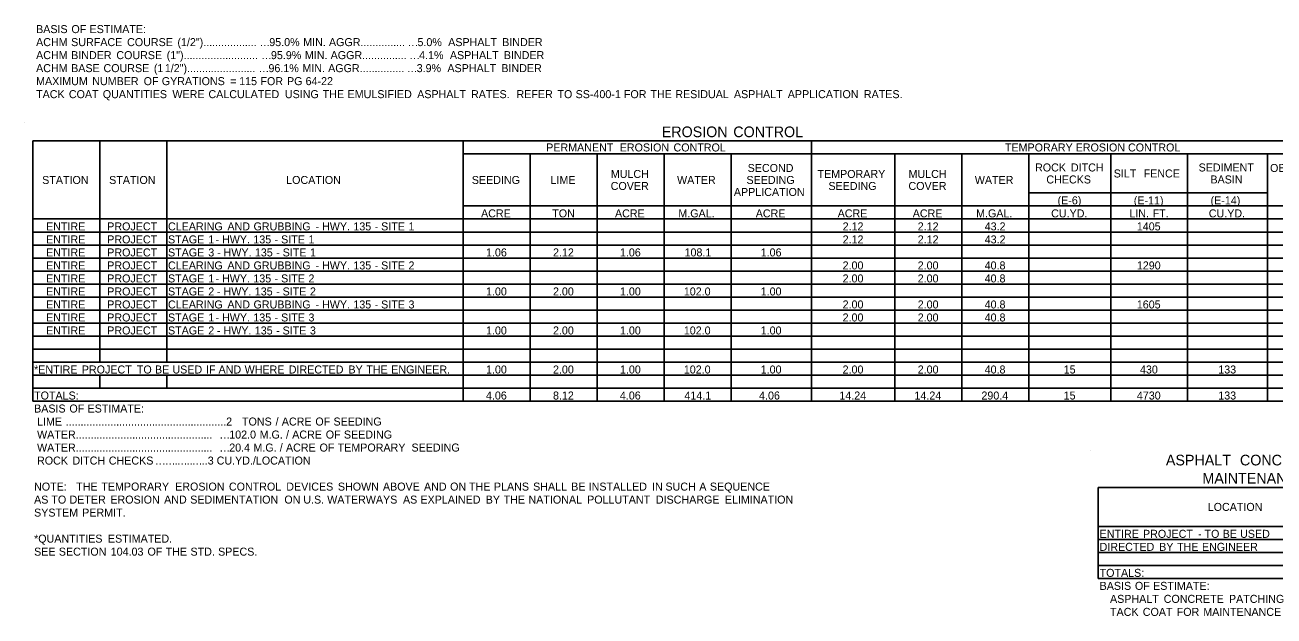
# Model space of a CAD drawing. Extents: x 1955554 to 1962042, y 565952 to 568347.
# Drawn here: x 1958686 to 1959623, y 566010 to 566453 of the extents above; entities that cross this region are included whole.
import ezdxf

# ---------------------------------------------------------------- set-up
doc = ezdxf.new("R2010")
doc.units = 0
doc.layers.add('Default', color=7, linetype='Continuous')
doc.layers.add('R_Border', color=7, linetype='Continuous')

msp = doc.modelspace()

# ---------------------------------------------------------------- linework, layer by layer
at = {"layer": 'Default'}
for p, q in [((1958692.33, 566365.86), (1959744.36, 566365.86)), ((1958692.33, 566170.86), (1958692.33, 566365.86)), ((1958692.33, 566170.86), (1958692.33, 566365.86)), ((1958742.54, 566200.11), (1958742.54, 566365.86)), ((1958792.76, 566200.11), (1958792.76, 566365.86)), ((1959015.06, 566170.86), (1959015.06, 566365.86)), ((1959276.36, 566356.11), (1959276.36, 566365.86)), ((1959276.36, 566170.86), (1959276.36, 566365.86)), ((1959015.06, 566356.11), (1959744.36, 566356.11)), ((1959065.27, 566170.86), (1959065.27, 566356.11)), ((1959115.48, 566170.86), (1959115.48, 566356.11)), ((1959165.69, 566170.86), (1959165.69, 566356.11)), ((1959215.91, 566170.86), (1959215.91, 566356.11)), ((1959338.76, 566170.86), (1959338.76, 566356.11)), ((1959388.97, 566170.86), (1959388.97, 566356.11)), ((1959439.18, 566170.86), (1959439.18, 566356.11)), ((1959500.61, 566170.86), (1959500.61, 566356.11)), ((1959558.13, 566170.86), (1959558.13, 566356.11)), ((1959618.09, 566170.86), (1959618.09, 566356.11)), ((1959439.18, 566326.86), (1959618.09, 566326.86)), ((1959558.13, 566326.86), (1959618.09, 566326.86)), ((1959015.06, 566317.11), (1959744.36, 566317.11)), ((1959065.27, 566170.86), (1959065.27, 566317.11)), ((1959115.48, 566180.61), (1959115.48, 566317.11)), ((1959165.69, 566180.61), (1959165.69, 566317.11)), ((1959215.91, 566180.61), (1959215.91, 566317.11)), ((1959276.36, 566180.61), (1959276.36, 566317.11)), ((1959338.76, 566170.86), (1959338.76, 566317.11)), ((1959388.97, 566170.86), (1959388.97, 566317.11)), ((1959439.18, 566180.61), (1959439.18, 566317.11)), ((1959500.61, 566180.61), (1959500.61, 566317.11)), ((1959558.13, 566170.86), (1959558.13, 566317.11)), ((1959618.09, 566317.11), (1959744.36, 566317.11)), ((1959618.09, 566170.86), (1959618.09, 566317.11)), ((1958692.33, 566307.36), (1959744.36, 566307.36)), ((1958742.54, 566200.11), (1958742.54, 566307.36)), ((1958792.76, 566200.11), (1958792.76, 566307.36)), ((1959015.06, 566200.11), (1959015.06, 566307.36)), ((1958692.33, 566297.61), (1959744.36, 566297.61)), ((1958692.33, 566287.86), (1959744.36, 566287.86)), ((1958692.33, 566278.11), (1959744.36, 566278.11)), ((1958692.33, 566268.36), (1959744.36, 566268.36)), ((1958692.33, 566258.61), (1959744.36, 566258.61)), ((1958692.33, 566248.86), (1959744.36, 566248.86)), ((1958692.33, 566239.11), (1959744.36, 566239.11)), ((1958692.33, 566229.36), (1959744.36, 566229.36)), ((1958692.33, 566219.61), (1959744.36, 566219.61)), ((1958692.33, 566209.86), (1959744.36, 566209.86)), ((1958692.33, 566200.11), (1959744.36, 566200.11)), ((1958692.33, 566190.36), (1959744.36, 566190.36)), ((1958742.54, 566180.61), (1958742.54, 566190.36)), ((1958742.54, 566180.61), (1958742.54, 566190.36)), ((1958792.76, 566180.61), (1958792.76, 566190.36)), ((1958792.76, 566180.61), (1958792.76, 566190.36)), ((1959015.06, 566170.86), (1959015.06, 566190.36)), ((1958692.33, 566180.61), (1959744.36, 566180.61)), ((1959065.27, 566180.61), (1959276.36, 566180.61)), ((1959276.36, 566180.61), (1959338.76, 566180.61)), ((1959338.76, 566180.61), (1959500.61, 566180.61)), ((1959500.61, 566180.61), (1959684.39, 566180.61)), ((1958692.33, 566170.86), (1959744.36, 566170.86)), ((1959491.34, 566106.2), (1959797.98, 566106.2)), ((1959491.34, 566037.95), (1959491.34, 566106.2)), ((1959491.34, 566037.95), (1959491.34, 566106.2)), ((1959491.34, 566076.95), (1959797.98, 566076.95)), ((1959491.34, 566067.2), (1959797.98, 566067.2)), ((1959491.34, 566057.45), (1959797.98, 566057.45)), ((1959491.34, 566047.7), (1959797.98, 566047.7)), ((1959491.34, 566037.95), (1959797.98, 566037.95))]:
    msp.add_line(p, q, dxfattribs=at)
at = {"layer": 'R_Border'}
for p, q in [((1958686.48, 566379.51), (1958686.48, 566379.51)), ((1959485.49, 566133.5), (1959485.49, 566133.5))]:
    msp.add_line(p, q, dxfattribs=at)

# ---------------------------------------------------------------- texts
at = {"layer": 'Default'}
for s, height, p in [('BASIS', 6, (1958694.82, 566446.67)), (' OF', 6, (1958719.08, 566446.67)), (' ESTIMATE:', 6, (1958732.67, 566446.67)), ('ACHM', 6, (1958694.82, 566436.92)), (' SURFACE', 6, (1958718.88, 566436.92)), (' COURSE', 6, (1958760.82, 566436.92)), (' (1/2")..................', 6, (1958798.57, 566436.92)), ('…', 6, (1958862.27, 566436.92)), ('95.0%', 6, (1958869.67, 566436.92)), (' MIN.', 6, (1958892.91, 566436.92)), (' AGGR...............', 6, (1958912.2, 566436.92)), ('…', 6, (1958973.4, 566436.92)), ('5.0%', 6, (1958980.8, 566436.92)), ('  ASPHALT', 6, (1958999.38, 566436.92)), (' BINDER', 6, (1959042.08, 566436.92)), ('ACHM', 6, (1958694.82, 566427.17)), (' BINDER', 6, (1958718.88, 566427.17)), (' COURSE', 6, (1958752.77, 566427.17)), (' (1").........................', 6, (1958790.52, 566427.17)), ('…', 6, (1958863.52, 566427.17)), ('95.9%', 6, (1958870.92, 566427.17)), (' MIN.', 6, (1958894.16, 566427.17)), (' AGGR...............', 6, (1958913.45, 566427.17)), ('…', 6, (1958974.66, 566427.17)), ('4.1%', 6, (1958982.06, 566427.17)), ('  ASPHALT', 6, (1959000.64, 566427.17)), (' BINDER', 6, (1959043.33, 566427.17)), ('ACHM', 6, (1958694.82, 566417.42)), (' BASE', 6, (1958718.88, 566417.42)), (' COURSE', 6, (1958743.13, 566417.42)), (' (1', 6, (1958780.88, 566417.42)), (' 1/2").......................', 6, (1958789.11, 566417.42)), ('…', 6, (1958861.66, 566417.42)), ('96.1%', 6, (1958869.06, 566417.42)), (' MIN.', 6, (1958892.3, 566417.42)), (' AGGR...............', 6, (1958911.59, 566417.42)), ('…', 6, (1958972.8, 566417.42)), ('3.9%', 6, (1958980.2, 566417.42)), ('  ASPHALT', 6, (1958998.78, 566417.42)), (' BINDER', 6, (1959041.47, 566417.42)), ('MAXIMUM', 6, (1958694.82, 566407.67)), (' NUMBER', 6, (1958734.71, 566407.67)), (' OF', 6, (1958773.25, 566407.67)), (' GYRATIONS', 6, (1958786.84, 566407.67)), (' =', 6, (1958838.11, 566407.67)), (' 115', 6, (1958844.87, 566407.67)), (' FOR', 6, (1958860.84, 566407.67)), (' PG', 6, (1958880.75, 566407.67)), (' 64-22', 6, (1958894.67, 566407.67)), ('TACK', 6, (1958694.82, 566397.92)), (' COAT', 6, (1958717.16, 566397.92)), (' QUANTITIES', 6, (1958742.61, 566397.92)), (' WERE', 6, (1958794.81, 566397.92)), (' CALCULATED', 6, (1958821.84, 566397.92)), (' USING', 6, (1958879.16, 566397.92)), (' THE', 6, (1958907.52, 566397.92)), (' EMULSIFIED', 6, (1958926.17, 566397.92)), (' ASPHALT', 6, (1958978.36, 566397.92)), (' RATES.', 6, (1959018.72, 566397.92)), ('  REFER', 6, (1959050.6, 566397.92)), (' TO', 6, (1959083.56, 566397.92)), (' SS-400-1', 6, (1959097.16, 566397.92)), (' FOR', 6, (1959133.35, 566397.92)), (' THE', 6, (1959153.26, 566397.92)), (' RESIDUAL', 6, (1959171.91, 566397.92)), (' ASPHALT', 6, (1959215.87, 566397.92)), (' APPLICATION', 6, (1959256.24, 566397.92)), (' RATES.', 6, (1959313.32, 566397.92)), ('EROSION', 8, (1959164, 566368.68)), (' CONTROL', 8, (1959214.66, 566368.68)), ('PERMANENT', 6, (1959077.32, 566357.98)), (' EROSION', 6, (1959130.25, 566357.98)), (' CONTROL', 6, (1959170.57, 566357.98)), ('TEMPORARY EROSION CONTROL', 6, (1959421.33, 566357.98)), ('MULCH', 6, (1959125.78, 566338.11)), ('SECOND', 6, (1959228.4, 566342.61)), ('TEMPORARY', 6, (1959280.77, 566338.11)), ('MULCH', 6, (1959349.05, 566338.11)), ('ROCK', 6, (1959443.91, 566342.98)), (' DITCH', 6, (1959468.58, 566342.98)), ('SILT', 6, (1959502.88, 566338.48)), ('  FENCE', 6, (1959520.87, 566338.48)), ('SEDIMENT', 6, (1959566.54, 566342.98)), ('OBLITERATION', 6, (1959620.14, 566342.61)), ('STATION', 6, (1958699.38, 566333.61)), ('STATION', 6, (1958749.59, 566333.61)), ('LOCATION', 6, (1958882.35, 566333.61)), ('SEEDING', 6, (1959021.55, 566333.61)), ('LIME', 6, (1959080.57, 566333.61)), ('COVER', 6, (1959125.7, 566329.11)), ('WATER', 6, (1959175.45, 566333.61)), ('SEEDING', 6, (1959227.52, 566333.61)), ('SEEDING', 6, (1959288.94, 566329.11)), ('COVER', 6, (1959348.98, 566329.11)), ('WATER', 6, (1959398.73, 566333.61)), ('CHECKS', 6, (1959452.4, 566333.98)), ('BASIN', 6, (1959575.41, 566333.98)), ('APPLICATION', 6, (1959218.06, 566324.61)), ('(E-6)', 6, (1959460.8, 566318.31)), ('(E-11)', 6, (1959517.95, 566318.31)), ('(E-14)', 6, (1959575.53, 566318.31)), ('ACRE', 6, (1959028.49, 566308.56)), ('TON', 6, (1959081.86, 566308.56)), ('ACRE', 6, (1959128.92, 566308.56)), ('M.GAL.', 6, (1959176.42, 566308.56)), ('ACRE', 6, (1959234.46, 566308.56)), ('ACRE', 6, (1959295.89, 566308.56)), ('ACRE', 6, (1959352.19, 566308.56)), ('M.GAL.', 6, (1959399.7, 566308.56)), ('CU.YD.', 6, (1959455.98, 566308.56)), ('LIN.', 6, (1959514.58, 566308.56)), (' FT.', 6, (1959529.84, 566308.56)), ('CU.YD.', 6, (1959574.19, 566308.56)), ('ENTIRE', 6, (1958702.29, 566298.81)), ('PROJECT', 6, (1958748.17, 566298.81)), ('CLEARING', 6, (1958793.73, 566298.81)), (' AND', 6, (1958836.07, 566298.81)), (' GRUBBING', 6, (1958855.65, 566298.81)), (' -', 6, (1958902.17, 566298.81)), (' HWY.', 6, (1958907.03, 566298.81)), (' 135', 6, (1958930.51, 566298.81)), (' -', 6, (1958946.49, 566298.81)), (' SITE', 6, (1958951.34, 566298.81)), (' 1', 6, (1958971.86, 566298.81)), ('2.12', 6, (1959299.62, 566298.81)), ('2.12', 6, (1959355.93, 566298.81)), ('43.2', 6, (1959406.14, 566298.81)), ('1405', 6, (1959520.22, 566298.81)), ('ENTIRE', 6, (1958702.29, 566289.06)), ('PROJECT', 6, (1958748.17, 566289.06)), ('STAGE', 6, (1958793.73, 566289.06)), (' 1', 6, (1958821.71, 566289.06)), (' -', 6, (1958827.15, 566289.06)), (' HWY.', 6, (1958832.01, 566289.06)), (' 135', 6, (1958855.49, 566289.06)), (' -', 6, (1958871.47, 566289.06)), (' SITE', 6, (1958876.32, 566289.06)), (' 1', 6, (1958896.84, 566289.06)), ('2.12', 6, (1959299.62, 566289.06)), ('2.12', 6, (1959355.93, 566289.06)), ('43.2', 6, (1959406.14, 566289.06)), ('ENTIRE', 6, (1958702.29, 566279.31)), ('PROJECT', 6, (1958748.17, 566279.31)), ('STAGE', 6, (1958793.73, 566279.31)), (' 3', 6, (1958821.71, 566279.31)), (' -', 6, (1958828.31, 566279.31)), (' HWY.', 6, (1958833.17, 566279.31)), (' 135', 6, (1958856.65, 566279.31)), (' -', 6, (1958872.63, 566279.31)), (' SITE', 6, (1958877.49, 566279.31)), (' 1', 6, (1958898, 566279.31)), ('1.06', 6, (1959032.2, 566279.31)), ('2.12', 6, (1959082.44, 566279.31)), ('1.06', 6, (1959132.62, 566279.31)), ('108.1', 6, (1959181.09, 566279.31)), ('1.06', 6, (1959238.17, 566279.31)), ('ENTIRE', 6, (1958702.29, 566269.56)), ('PROJECT', 6, (1958748.17, 566269.56)), ('CLEARING', 6, (1958793.73, 566269.56)), (' AND', 6, (1958836.07, 566269.56)), (' GRUBBING', 6, (1958855.65, 566269.56)), (' -', 6, (1958902.17, 566269.56)), (' HWY.', 6, (1958907.03, 566269.56)), (' 135', 6, (1958930.51, 566269.56)), (' -', 6, (1958946.49, 566269.56)), (' SITE', 6, (1958951.34, 566269.56)), (' 2', 6, (1958971.86, 566269.56)), ('2.00', 6, (1959299.6, 566269.56)), ('2.00', 6, (1959355.91, 566269.56)), ('40.8', 6, (1959406.11, 566269.56)), ('1290', 6, (1959520.25, 566269.56)), ('ENTIRE', 6, (1958702.29, 566259.81)), ('PROJECT', 6, (1958748.17, 566259.81)), ('STAGE', 6, (1958793.73, 566259.81)), (' 1', 6, (1958821.71, 566259.81)), (' -', 6, (1958827.15, 566259.81)), (' HWY.', 6, (1958832.01, 566259.81)), (' 135', 6, (1958855.49, 566259.81)), (' -', 6, (1958871.47, 566259.81)), (' SITE', 6, (1958876.32, 566259.81)), (' 2', 6, (1958896.84, 566259.81)), ('2.00', 6, (1959299.6, 566259.81)), ('2.00', 6, (1959355.91, 566259.81)), ('40.8', 6, (1959406.11, 566259.81)), ('ENTIRE', 6, (1958702.29, 566250.06)), ('PROJECT', 6, (1958748.17, 566250.06)), ('STAGE', 6, (1958793.73, 566250.06)), (' 2', 6, (1958821.71, 566250.06)), (' -', 6, (1958828.25, 566250.06)), (' HWY.', 6, (1958833.11, 566250.06)), (' 135', 6, (1958856.59, 566250.06)), (' -', 6, (1958872.56, 566250.06)), (' SITE', 6, (1958877.42, 566250.06)), (' 2', 6, (1958897.94, 566250.06)), ('1.00', 6, (1959032.21, 566250.06)), ('2.00', 6, (1959082.42, 566250.06)), ('1.00', 6, (1959132.64, 566250.06)), ('102.0', 6, (1959180.52, 566250.06)), ('1.00', 6, (1959238.18, 566250.06)), ('ENTIRE', 6, (1958702.29, 566240.31)), ('PROJECT', 6, (1958748.17, 566240.31)), ('CLEARING', 6, (1958793.73, 566240.31)), (' AND', 6, (1958836.07, 566240.31)), (' GRUBBING', 6, (1958855.65, 566240.31)), (' -', 6, (1958902.17, 566240.31)), (' HWY.', 6, (1958907.03, 566240.31)), (' 135', 6, (1958930.51, 566240.31)), (' -', 6, (1958946.49, 566240.31)), (' SITE', 6, (1958951.34, 566240.31)), (' 3', 6, (1958971.86, 566240.31)), ('2.00', 6, (1959299.6, 566240.31)), ('2.00', 6, (1959355.91, 566240.31)), ('40.8', 6, (1959406.11, 566240.31)), ('1605', 6, (1959520.22, 566240.31)), ('ENTIRE', 6, (1958702.29, 566230.56)), ('PROJECT', 6, (1958748.17, 566230.56)), ('STAGE', 6, (1958793.73, 566230.56)), (' 1', 6, (1958821.71, 566230.56)), (' -', 6, (1958827.15, 566230.56)), (' HWY.', 6, (1958832.01, 566230.56)), (' 135', 6, (1958855.49, 566230.56)), (' -', 6, (1958871.47, 566230.56)), (' SITE', 6, (1958876.32, 566230.56)), (' 3', 6, (1958896.84, 566230.56)), ('2.00', 6, (1959299.6, 566230.56)), ('2.00', 6, (1959355.91, 566230.56)), ('40.8', 6, (1959406.11, 566230.56)), ('ENTIRE', 6, (1958702.29, 566220.81)), ('PROJECT', 6, (1958748.17, 566220.81)), ('STAGE', 6, (1958793.73, 566220.81)), (' 2', 6, (1958821.71, 566220.81)), (' -', 6, (1958828.25, 566220.81)), (' HWY.', 6, (1958833.11, 566220.81)), (' 135', 6, (1958856.59, 566220.81)), (' -', 6, (1958872.56, 566220.81)), (' SITE', 6, (1958877.42, 566220.81)), (' 3', 6, (1958897.94, 566220.81)), ('1.00', 6, (1959032.21, 566220.81)), ('2.00', 6, (1959082.42, 566220.81)), ('1.00', 6, (1959132.64, 566220.81)), ('102.0', 6, (1959180.52, 566220.81)), ('1.00', 6, (1959238.18, 566220.81)), ('*ENTIRE', 6, (1958693.31, 566191.56)), (' PROJECT', 6, (1958726.87, 566191.56)), (' TO', 6, (1958768.16, 566191.56)), (' BE', 6, (1958781.75, 566191.56)), (' USED', 6, (1958794.82, 566191.56)), (' IF', 6, (1958819.99, 566191.56)), (' AND', 6, (1958829.39, 566191.56)), (' WHERE', 6, (1958848.97, 566191.56)), (' DIRECTED', 6, (1958882.06, 566191.56)), (' BY', 6, (1958926.79, 566191.56)), (' THE', 6, (1958940.24, 566191.56)), (' ENGINEER.', 6, (1958958.89, 566191.56)), ('1.00', 6, (1959032.21, 566191.56)), ('2.00', 6, (1959082.42, 566191.56)), ('1.00', 6, (1959132.64, 566191.56)), ('102.0', 6, (1959180.52, 566191.56)), ('1.00', 6, (1959238.18, 566191.56)), ('2.00', 6, (1959299.6, 566191.56)), ('2.00', 6, (1959355.91, 566191.56)), ('40.8', 6, (1959406.11, 566191.56)), ('15', 6, (1959465.4, 566191.56)), ('430', 6, (1959522.58, 566191.56)), ('133', 6, (1959581.31, 566191.56)), ('TOTALS:', 6, (1958693.31, 566172.06)), ('4.06', 6, (1959032.16, 566172.06)), ('8.12', 6, (1959082.43, 566172.06)), ('4.06', 6, (1959132.58, 566172.06)), ('414.1', 6, (1959181, 566172.06)), ('4.06', 6, (1959236.96, 566172.06)), ('14.24', 6, (1959297.17, 566172.06)), ('14.24', 6, (1959353.48, 566172.06)), ('290.4', 6, (1959403.69, 566172.06)), ('15', 6, (1959465.36, 566172.06)), ('4730', 6, (1959520.26, 566172.06)), ('133', 6, (1959581.3, 566172.06)), ('BASIS', 6, (1958693.31, 566162.31)), (' OF', 6, (1958717.57, 566162.31)), (' ESTIMATE:', 6, (1958731.15, 566162.31)), (' LIME', 6, (1958693.31, 566152.56)), (' ......................................................2', 6, (1958714.75, 566152.56)), (' TONS', 6, (1958846.99, 566152.56)), (' /', 6, (1958872.17, 566152.56)), (' ACRE', 6, (1958876.83, 566152.56)), (' OF', 6, (1958902.01, 566152.56)), (' SEEDING', 6, (1958915.6, 566152.56)), (' WATER..............................................', 6, (1958693.31, 566142.81)), ('102.0', 6, (1958839.65, 566142.81)), (' M.G.', 6, (1958860.22, 566142.81)), (' /', 6, (1958879.97, 566142.81)), (' ACRE', 6, (1958884.63, 566142.81)), (' OF', 6, (1958909.81, 566142.81)), (' SEEDING', 6, (1958923.4, 566142.81)), (' WATER..............................................', 6, (1958693.31, 566133.06)), ('…', 6, (1958832.25, 566142.81)), ('20.4', 6, (1958839.65, 566133.06)), (' M.G.', 6, (1958855.55, 566133.06)), (' /', 6, (1958875.31, 566133.06)), (' ACRE', 6, (1958879.97, 566133.06)), (' OF', 6, (1958905.15, 566133.06)), (' TEMPORARY', 6, (1958918.73, 566133.06)), (' SEEDING', 6, (1958974.1, 566133.06)), (' ROCK', 6, (1958693.31, 566123.31)), (' DITCH', 6, (1958719.84, 566123.31)), (' CHECKS', 6, (1958747.11, 566123.31)), ('..3', 6, (1958819.06, 566123.31)), (' CU.YD./LOCATION', 6, (1958827.99, 566123.31)), ('…', 6, (1958832.25, 566133.06)), ('ASPHALT', 8, (1959542.02, 566122.67)), (' CONCRETE', 8, (1959594.58, 566122.67)), ('…', 6, (1958783.94, 566123.31)), ('…', 6, (1958791.34, 566123.31)), ('.', 6, (1958798.74, 566123.31)), ('…', 6, (1958800.33, 566123.31)), ('..', 6, (1958807.73, 566123.31)), ('…', 6, (1958811.66, 566123.31)), ('NOTE:', 6, (1958693.31, 566103.81)), ('   THE', 6, (1958718.19, 566103.81)), (' TEMPORARY', 6, (1958741.5, 566103.81)), (' EROSION', 6, (1958796.87, 566103.81)), (' CONTROL', 6, (1958837.18, 566103.81)), (' DEVICES', 6, (1958880.2, 566103.81)), (' SHOWN', 6, (1958918.9, 566103.81)), (' ABOVE', 6, (1958952.67, 566103.81)), (' AND', 6, (1958983.45, 566103.81)), (' ON', 6, (1959003.03, 566103.81)), (' THE', 6, (1959017.25, 566103.81)), (' PLANS', 6, (1959035.9, 566103.81)), (' SHALL', 6, (1959065.28, 566103.81)), (' BE', 6, (1959093.87, 566103.81)), (' INSTALLED', 6, (1959106.94, 566103.81)), (' IN', 6, (1959154.47, 566103.81)), (' SUCH', 6, (1959164.5, 566103.81)), (' A', 6, (1959189.91, 566103.81)), (' SEQUENCE', 6, (1959197.84, 566103.81)), ('MAINTENANCE', 8, (1959569.42, 566109.02)), ('AS', 6, (1958693.31, 566094.06)), (' TO', 6, (1958704.05, 566094.06)), (' DETER', 6, (1958717.65, 566094.06)), (' EROSION', 6, (1958748.28, 566094.06)), (' AND', 6, (1958788.59, 566094.06)), (' SEDIMENTATION', 6, (1958808.17, 566094.06)), (' ON', 6, (1958878.75, 566094.06)), (' U.S.', 6, (1958892.97, 566094.06)), (' WATERWAYS', 6, (1958910.87, 566094.06)), (' AS', 6, (1958967.72, 566094.06)), (' EXPLAINED', 6, (1958980.8, 566094.06)), (' BY', 6, (1959029.74, 566094.06)), (' THE', 6, (1959043.19, 566094.06)), (' NATIONAL', 6, (1959061.84, 566094.06)), (' POLLUTANT', 6, (1959105.8, 566094.06)), (' DISCHARGE', 6, (1959157.34, 566094.06)), (' ELIMINATION', 6, (1959209.06, 566094.06)), ('SYSTEM', 6, (1958693.31, 566084.31)), (' PERMIT.', 6, (1958727.15, 566084.31)), ('LOCATION', 6, (1959573.39, 566088.57)), ('ENTIRE', 6, (1959492.32, 566068.4)), (' PROJECT', 6, (1959522.62, 566068.4)), (' TO', 6, (1959568.76, 566068.4)), (' BE', 6, (1959582.36, 566068.4)), (' USED', 6, (1959595.43, 566068.4)), ('*QUANTITIES', 6, (1958693.31, 566064.81)), (' ESTIMATED.', 6, (1958746.44, 566064.81)), ('DIRECTED', 6, (1959492.32, 566058.65)), (' BY', 6, (1959534.73, 566058.65)), (' THE', 6, (1959548.18, 566058.65)), (' -', 6, (1959563.91, 566068.4)), (' ENGINEER', 6, (1959566.83, 566058.65)), ('SEE', 6, (1958693.31, 566055.06)), (' SECTION', 6, (1958709.64, 566055.06)), (' 104.03', 6, (1958748.55, 566055.06)), (' OF', 6, (1958776.12, 566055.06)), (' THE', 6, (1958789.71, 566055.06)), (' STD.', 6, (1958808.36, 566055.06)), (' SPECS.', 6, (1958829.05, 566055.06)), ('TOTALS:', 6, (1959492.32, 566039.15)), ('BASIS', 6, (1959492.32, 566029.4)), (' OF', 6, (1959516.58, 566029.4)), (' ESTIMATE:', 6, (1959530.17, 566029.4)), ('ASPHALT', 6, (1959500.12, 566019.65)), (' CONCRETE', 6, (1959538.16, 566019.65)), (' PATCHING', 6, (1959587.09, 566019.65)), ('TACK', 6, (1959500.12, 566009.9)), (' COAT', 6, (1959522.46, 566009.9)), (' FOR', 6, (1959547.91, 566009.9)), (' MAINTENANCE', 6, (1959567.83, 566009.9))]:
    msp.add_text(s, height=height, dxfattribs=at).set_placement(p)

doc.saveas('drawing.dxf')
